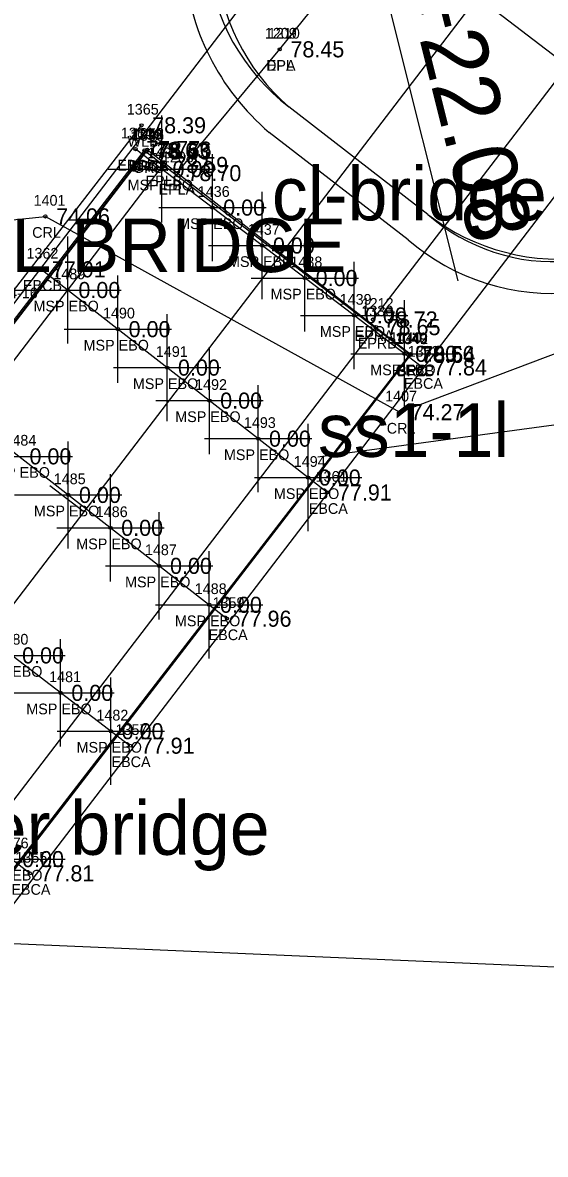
# Model space of a CAD drawing. Extents: x 2500794 to 2511032, y 910653 to 917533.
# Drawn here: x 2506099.6 to 2506148.4, y 913842.2 to 913947.8 of the extents above; entities that cross this region are included whole.
import ezdxf

# ---------------------------------------------------------------- set-up
doc = ezdxf.new("R2010")
doc.units = 0
for name, color, linetype in [('Default', 7, 'Continuous'), ('RD_EX_BldgApp', 7, 'Continuous'), ('RD_EX_Bridge', 7, 'Continuous'), ('RD_EX_Bridge_txCode', 7, 'Continuous'), ('RD_EX_Driveway_txCode', 7, 'Continuous'), ('RD_EX_GuardRail', 7, 'Continuous'), ('RD_EX_GuardRail_txCode', 7, 'Continuous'), ('RD_EX_H2O', 7, 'Continuous'), ('RD_EX_H2O_txCode', 7, 'Continuous'), ('RD_EX_Misc', 7, 'Continuous'), ('RD_EX_Misc_txCode', 7, 'Continuous'), ('RD_EX_Road', 7, 'Continuous'), ('RD_EX_Road_txCode', 7, 'Continuous'), ('RD_EX_TX_Bridge_ELEV', 7, 'Continuous'), ('RD_EX_TX_Driveway_ELEV', 7, 'Continuous'), ('RD_EX_TX_GuardRail_ELEV', 7, 'Continuous'), ('RD_EX_TX_H2O_ELEV', 7, 'Continuous'), ('RD_EX_TX_Misc_ELEV', 7, 'Continuous'), ('RD_EX_TX_Road_ELEV', 7, 'Continuous'), ('RD_EX_TX_UT_ELEV', 7, 'Continuous'), ('RD_EX_UT_txCode', 7, 'Continuous'), ('RD_HC_Cl', 7, 'Continuous'), ('RD_HC_Data', 7, 'Continuous'), ('RD_HC_Data_Tic', 7, 'Continuous'), ('RD_PD_Bridge', 7, 'Continuous'), ('RD_PD_CstnLmt', 7, 'Continuous'), ('RD_PD_Signals', 7, 'Continuous'), ('RD_SMD_Locator', 7, 'Continuous'), ('RD_XS_NPDES', 7, 'Continuous')]:
    doc.layers.add(name, color=color, linetype=linetype)

# ---------------------------------------------------------------- blocks, each defined once
blk = doc.blocks.new('POINT_DISPLAY')
at = {"layer": 'Default'}
blk.add_line((0, 0), (0, 0), dxfattribs=at)
blk = doc.blocks.new('Non-Wetland Waters (Tributaries)')
at = {"layer": 'Default'}
blk.add_lwpolyline([(636556.303, 232132.46), (636575.915, 232135.121), (636589.015, 232131.251), (636595.56, 232130.161)], dxfattribs=at)

msp = doc.modelspace()

# ---------------------------------------------------------------- linework, layer by layer
at = {"layer": 'RD_EX_BldgApp'}
msp.add_line((2506016.51, 913816.53), (2506110.72, 913938.26), dxfattribs=at)
at = {"layer": 'RD_EX_Bridge'}
for p, q in [((2506136.91, 913915.67), (2506110.17, 913936.04)), ((2506128.04, 913904), (2506101.37, 913924.82)), ((2506118.69, 913892.22), (2506092.16, 913912.92)), ((2506109.65, 913880.37), (2506082.8, 913900.86)), ((2506100.31, 913868.46), (2506073.74, 913889.05))]:
    msp.add_line(p, q, dxfattribs=at)
for points in [[(2506044.21, 913797.79), (2506019.43, 913816.8), (2506111, 913935.92), (2506135.82, 913916.84), (2506044.21, 913797.79)], [(2506111.24, 913935.99), (2506135.76, 913916.92), (2506044.08, 913798.01), (2506019.65, 913816.86), (2506111.24, 913935.99)]]:
    msp.add_lwpolyline(points, dxfattribs=at)
at = {"layer": 'RD_EX_GuardRail'}
for p, q in [((2506019.73, 913816.87), (2506111.18, 913935.82)), ((2506044.2, 913797.96), (2506135.82, 913916.84))]:
    msp.add_line(p, q, dxfattribs=at)
at = {"layer": 'RD_EX_H2O_txCode'}
msp.add_lwpolyline([(2505808.2, 913925.07), (2505825.64, 913915.36), (2505914.54, 913915.98), (2505996.26, 913926.38), (2506005.4, 913936.74), (2506012.64, 913937.08), (2506022.61, 913935.73), (2506047.54, 913912.75), (2506069, 913926.42), (2506101.76, 913929.76), (2506134.82, 913911.49), (2506168.31, 913924.14), (2506205.52, 913926.29), (2506300.04, 913899.96), (2506387.24, 913834.45), (2506403.62, 913708.7), (2506351.33, 913635.45), (2506287.73, 913577.34)], dxfattribs=at)
at = {"layer": 'RD_EX_Misc'}
for p, q in [((2506112.62, 913929.18), (2506112.62, 913939.18)), ((2506117.34, 913925.58), (2506117.34, 913935.58)), ((2506107.62, 913934.18), (2506117.62, 913934.18)), ((2506121.98, 913922.04), (2506121.98, 913932.04)), ((2506112.34, 913930.58), (2506122.34, 913930.58)), ((2506125.96, 913919.01), (2506125.96, 913929.01)), ((2506103.84, 913917.89), (2506103.84, 913927.89)), ((2506116.98, 913927.04), (2506126.98, 913927.04)), ((2506130.55, 913915.52), (2506130.55, 913925.52)), ((2506108.52, 913914.24), (2506108.52, 913924.24)), ((2506120.96, 913924.01), (2506130.96, 913924.01)), ((2506098.84, 913922.89), (2506108.84, 913922.89)), ((2506135.24, 913911.94), (2506135.24, 913921.94)), ((2506113.12, 913910.65), (2506113.12, 913920.65)), ((2506125.55, 913920.52), (2506135.55, 913920.52)), ((2506103.52, 913919.24), (2506113.52, 913919.24)), ((2506117.06, 913907.57), (2506117.06, 913917.57)), ((2506130.24, 913916.94), (2506140.24, 913916.94)), ((2506108.12, 913915.65), (2506118.12, 913915.65)), ((2506121.61, 913904.02), (2506121.61, 913914.02)), ((2506112.06, 913912.57), (2506122.06, 913912.57)), ((2506126.26, 913900.39), (2506126.26, 913910.39)), ((2506103.89, 913898.77), (2506103.89, 913908.77)), ((2506116.61, 913909.02), (2506126.61, 913909.02)), ((2506094.28, 913907.37), (2506104.28, 913907.37)), ((2506107.83, 913895.7), (2506107.83, 913905.7)), ((2506121.26, 913905.39), (2506131.26, 913905.39)), ((2506098.89, 913903.77), (2506108.89, 913903.77)), ((2506112.38, 913892.15), (2506112.38, 913902.15)), ((2506102.83, 913900.7), (2506112.83, 913900.7)), ((2506117.04, 913888.52), (2506117.04, 913898.52)), ((2506107.38, 913897.15), (2506117.38, 913897.15)), ((2506112.04, 913893.52), (2506122.04, 913893.52)), ((2506103.18, 913880.3), (2506103.18, 913890.3)), ((2506093.59, 913888.8), (2506103.59, 913888.8)), ((2506107.87, 913876.72), (2506107.87, 913886.72)), ((2506098.18, 913885.3), (2506108.18, 913885.3)), ((2506102.87, 913881.72), (2506112.87, 913881.72)), ((2506093.59, 913869.79), (2506103.59, 913869.79))]:
    msp.add_line(p, q, dxfattribs=at)
at = {"layer": 'RD_EX_Road'}
for points in [[(2506114.01, 913933.8), (2506123.61, 913945.35), (2506183.7, 914019.9), (2506246.75, 914102.24), (2506309.52, 914184.62), (2506366.78, 914260.38), (2506431.55, 914345.25), (2506455.95, 914376.74), (2506469.75, 914395.23), (2506492.7, 914425.08), (2506555.84, 914508.26), (2506617.75, 914589.02), (2506679.77, 914670.81), (2506740.35, 914750.22)], [(2506132.31, 913920.14), (2506200.99, 914009.83), (2506228.78, 914046.14), (2506238.19, 914058.36), (2506261.83, 914089.97), (2506324.5, 914172.22), (2506382.84, 914247.97), (2506424.88, 914303.73), (2506446.4, 914331.89), (2506508.34, 914413.09), (2506571.21, 914495.53), (2506633.01, 914576.81), (2506694.83, 914657.95), (2506756.78, 914739.18)], [(2506022.41, 913814.76), (2506062.45, 913868.71), (2506112.78, 913934.56)], [(2506041.83, 913800.29), (2506083.18, 913854.87), (2506132.58, 913919.43)]]:
    msp.add_lwpolyline(points, dxfattribs=at)
at = {"layer": 'RD_HC_Cl'}
for p, q in [((2505807.57, 913512.69), (2506748.89, 914743.92)), ((2505870.76, 913871.61), (2506259.06, 913855.07))]:
    msp.add_line(p, q, dxfattribs=at)
at = {"layer": 'RD_HC_Data'}
msp.add_line((2506112.07, 914036.23), (2506140.23, 913923.75), dxfattribs=at)
at = {"layer": 'RD_HC_Data_Tic'}
msp.add_line((2506105.36, 913902.19), (2506102.18, 913904.62), dxfattribs=at)
at = {"layer": 'RD_PD_Bridge'}
for p, q in [((2506007.09, 913801.65), (2506128.56, 913960.53)), ((2506155.57, 913939.88), (2506128.56, 913960.53)), ((2506034.1, 913781), (2506155.57, 913939.88))]:
    msp.add_line(p, q, dxfattribs=at)
at = {"layer": 'RD_PD_CstnLmt'}
msp.add_line((2506137.42, 913929.95), (2506124.47, 913939.97), dxfattribs=at)
for centre, radius, start, end in [((2506137.24, 913954.83), 19.59, 137.0924, 229.3275), ((2506149.09, 913943.18), 17.64, 228.5809, 321.497)]:
    msp.add_arc(centre, radius, start, end, dxfattribs=at)
at = {"layer": 'RD_PD_Signals'}
msp.add_line((2506137.42, 913929.95), (2506124.47, 913939.97), dxfattribs=at)
for centre, start, end in [((2506136.71, 913955.79), 140.0354, 232.2705), ((2506149.66, 913945.77), 232.2705, 325.1865)]:
    msp.add_arc(centre, 20, start, end, dxfattribs=at)
at = {"layer": 'RD_SMD_Locator'}
for centre in [(2506123.61, 913945.35), (2506123.61, 913945.35), (2506110.72, 913938.26), (2506110.17, 913936.04), (2506111, 913935.92), (2506111.18, 913935.82), (2506111.24, 913935.99), (2506111.24, 913935.99), (2506112.78, 913934.56), (2506112.62, 913934.18), (2506114.01, 913933.8), (2506117.34, 913930.58), (2506101.76, 913929.76), (2506121.98, 913927.04), (2506101.37, 913924.82), (2506125.96, 913924.01), (2506103.84, 913922.89), (2506130.55, 913920.52), (2506132.31, 913920.14), (2506108.52, 913919.24), (2506132.58, 913919.43), (2506135.24, 913916.94), (2506135.76, 913916.92), (2506135.82, 913916.84), (2506135.82, 913916.84), (2506113.12, 913915.65), (2506136.91, 913915.67), (2506117.06, 913912.57), (2506134.82, 913911.49), (2506121.61, 913909.02), (2506126.26, 913905.39), (2506103.89, 913903.77), (2506128.04, 913904), (2506107.83, 913900.7), (2506112.38, 913897.15), (2506117.04, 913893.52), (2506118.69, 913892.22), (2506103.18, 913885.3), (2506107.87, 913881.72), (2506109.65, 913880.37), (2506100.31, 913868.46)]:
    msp.add_circle(centre, 0.15, dxfattribs=at)
at = {"layer": 'RD_XS_NPDES'}
msp.add_line((2506135.58, 913927.58), (2506122.64, 913937.6), dxfattribs=at)
for centre, radius, start, end in [((2506137.26, 913954.83), 22.6, 137.4459, 229.681), ((2506149.08, 913943.2), 20.64, 229.1605, 322.0766)]:
    msp.add_arc(centre, radius, start, end, dxfattribs=at)

# ---------------------------------------------------------------- block references
at = {"layer": 'Default', "xscale": 3.937007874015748, "yscale": 3.937007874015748}
for name, p in [('Non-Wetland Waters (Tributaries)', (0, 0)), ('POINT_DISPLAY', (2506122.88, 913929.39)), ('POINT_DISPLAY', (2506122.88, 913929.39)), ('POINT_DISPLAY', (2506127.18, 913907.32)), ('POINT_DISPLAY', (2506127.18, 913907.32))]:
    msp.add_blockref(name, p, dxfattribs=at)
at = {"layer": 'RD_EX_H2O', "xscale": 3.937007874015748, "yscale": 3.937007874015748}
msp.add_blockref('Non-Wetland Waters (Tributaries)', (0, 0), dxfattribs=at)

# ---------------------------------------------------------------- texts
at = {"layer": 'Default'}
for s, p in [('cl-bridge 1', (2506122.88, 913929.39)), ('cl-bridge 1', (2506122.88, 913929.39)), ('S2-9L BRIDGE', (2506084.48, 913924.56)), ('S2-9L BRIDGE', (2506084.48, 913924.56)), ('ss1-1l', (2506127.18, 913907.32)), ('ss1-1l', (2506127.18, 913907.32)), ('cl/center bridge', (2506076.96, 913870.19)), ('cl/center bridge', (2506076.96, 913870.19))]:
    msp.add_text(s, height=5, dxfattribs=at).set_placement(p)
at = {"layer": 'RD_EX_Bridge_txCode'}
for s, p in [('1364', (2506108.8, 913937.04)), ('1339', (2506109.66, 913936.92)), ('1048', (2506109.85, 913936.99)), ('1052', (2506109.85, 913936.99)), ('EBCB', (2506108.47, 913934.04)), ('BRCA', (2506109.5, 913933.99)), ('BRCB', (2506109.52, 913933.99)), ('BRC', (2506109.75, 913933.92)), ('1362', (2506100, 913925.82)), ('EBCB', (2506099.67, 913922.82)), ('1049', (2506134.38, 913917.92)), ('1340', (2506134.43, 913917.84)), ('1363', (2506135.54, 913916.67)), ('BRC', (2506134.51, 913914.92)), ('BRC', (2506134.56, 913914.84)), ('EBCA', (2506135.19, 913913.67)), ('1361', (2506126.95, 913905)), ('EBCA', (2506126.32, 913902)), ('1359', (2506117.35, 913893.22)), ('EBCA', (2506116.98, 913890.22)), ('1357', (2506108.3, 913881.37)), ('EBCA', (2506107.93, 913878.37)), ('1355', (2506098.96, 913869.46)), ('EBCA', (2506098.59, 913866.46))]:
    msp.add_text(s, height=1, dxfattribs=at).set_placement(p)
at = {"layer": 'RD_EX_Driveway_txCode'}
for s, p in [('1210', (2506122.51, 913946.35)), ('DPA', (2506122.34, 913943.35))]:
    msp.add_text(s, height=1, dxfattribs=at).set_placement(p)
at = {"layer": 'RD_EX_GuardRail_txCode'}
for s, p in [('1338', (2506109.83, 913936.82)), ('GRB', (2506109.92, 913933.82)), ('1342', (2506134.47, 913917.84)), ('GR1B', (2506134.4, 913914.84))]:
    msp.add_text(s, height=1, dxfattribs=at).set_placement(p)
at = {"layer": 'RD_EX_H2O_txCode'}
for s, p in [('1401', (2506100.66, 913930.76)), ('CRL', (2506100.53, 913927.76)), ('odw  12-14-16', (2506092.5, 913922.12)), ('1407', (2506133.44, 913912.49)), ('CRL', (2506133.59, 913909.49))]:
    msp.add_text(s, height=1, dxfattribs=at).set_placement(p)
at = {"layer": 'RD_EX_Misc_txCode'}
for s, p in [('1435', (2506111.28, 913935.18)), ('MSP EBO', (2506109.43, 913932.18)), ('1436', (2506115.97, 913931.58)), ('MSP EBO', (2506114.14, 913928.58)), ('1437', (2506120.64, 913928.04)), ('MSP EBO', (2506118.79, 913925.04)), ('1438', (2506124.61, 913925.01)), ('1489', (2506102.5, 913923.89)), ('MSP EBO', (2506122.76, 913922.01)), ('MSP EBO', (2506100.65, 913920.89)), ('1439', (2506129.2, 913921.52)), ('1490', (2506107.13, 913920.24)), ('MSP EBO', (2506127.35, 913918.52)), ('1440', (2506133.86, 913917.94)), ('MSP EBO', (2506105.32, 913917.24)), ('1491', (2506112.06, 913916.65)), ('MSP EBO', (2506132.05, 913914.94)), ('MSP EBO', (2506109.92, 913913.65)), ('1492', (2506115.72, 913913.57)), ('MSP EBO', (2506113.87, 913910.57)), ('1493', (2506120.27, 913910.02)), ('1484', (2506097.94, 913908.37)), ('MSP EBO', (2506118.41, 913907.02)), ('1494', (2506124.92, 913906.39)), ('MSP EBO', (2506096.09, 913905.37)), ('1485', (2506102.54, 913904.77)), ('MSP EBO', (2506123.07, 913903.39)), ('MSP EBO', (2506100.69, 913901.77)), ('1486', (2506106.46, 913901.7)), ('MSP EBO', (2506104.64, 913898.7)), ('1487', (2506111.04, 913898.15)), ('MSP EBO', (2506109.19, 913895.15)), ('1488', (2506115.69, 913894.52)), ('MSP EBO', (2506113.84, 913891.52)), ('1480', (2506097.2, 913889.8)), ('MSP EBO', (2506095.39, 913886.8)), ('1481', (2506102.11, 913886.3)), ('MSP EBO', (2506099.98, 913883.3)), ('1482', (2506106.52, 913882.72)), ('MSP EBO', (2506104.67, 913879.72)), ('1476', (2506097.22, 913870.79)), ('MSP EBO', (2506095.4, 913867.79))]:
    msp.add_text(s, height=1, dxfattribs=at).set_placement(p)
at = {"layer": 'RD_EX_Road_txCode'}
for s, p in [('1209', (2506122.22, 913946.35)), ('EPL', (2506122.4, 913943.35)), ('1337', (2506111.44, 913935.56)), ('1208', (2506112.62, 913934.8)), ('EPLB', (2506111.1, 913932.56)), ('EPLA', (2506112.31, 913931.8)), ('1212', (2506131.25, 913921.14)), ('1336', (2506131.21, 913920.43)), ('EPRA', (2506130.59, 913918.14)), ('EPRB', (2506130.88, 913917.43))]:
    msp.add_text(s, height=1, dxfattribs=at).set_placement(p)
at = {"layer": 'RD_EX_TX_Bridge_ELEV'}
for s, p in [('77.77', (2506111.17, 913935.29)), ('78.63', (2506112, 913935.17)), ('78.56', (2506112.24, 913935.24)), ('78.56', (2506112.24, 913935.24)), ('77.91', (2506102.37, 913924.07)), ('78.56', (2506136.76, 913916.17)), ('78.64', (2506136.82, 913916.09)), ('77.84', (2506137.91, 913914.92)), ('77.91', (2506129.04, 913903.25)), ('77.96', (2506119.69, 913891.47)), ('77.91', (2506110.65, 913879.62)), ('77.81', (2506101.31, 913867.71))]:
    msp.add_text(s, height=1.5, dxfattribs=at).set_placement(p)
at = {"layer": 'RD_EX_TX_Driveway_ELEV'}
msp.add_text('78.45', height=1.5, dxfattribs=at).set_placement((2506124.61, 913944.6))
at = {"layer": 'RD_EX_TX_GuardRail_ELEV'}
for s, p in [('78.63', (2506112.18, 913935.07)), ('78.64', (2506136.82, 913916.09))]:
    msp.add_text(s, height=1.5, dxfattribs=at).set_placement(p)
at = {"layer": 'RD_EX_TX_H2O_ELEV'}
for s, p in [('74.06', (2506102.76, 913929.01)), ('74.27', (2506135.82, 913910.74))]:
    msp.add_text(s, height=1.5, dxfattribs=at).set_placement(p)
at = {"layer": 'RD_EX_TX_Misc_ELEV'}
for p in [(2506113.62, 913933.43), (2506118.34, 913929.83), (2506122.98, 913926.29), (2506126.96, 913923.26), (2506104.84, 913922.14), (2506131.55, 913919.77), (2506109.52, 913918.49), (2506136.24, 913916.19), (2506114.12, 913914.9), (2506118.06, 913911.82), (2506122.61, 913908.27), (2506100.28, 913906.62), (2506127.26, 913904.64), (2506104.89, 913903.02), (2506108.83, 913899.95), (2506113.38, 913896.4), (2506118.04, 913892.77), (2506099.59, 913888.05), (2506104.18, 913884.55), (2506108.87, 913880.97), (2506099.59, 913869.04)]:
    msp.add_text('0.00', height=1.5, dxfattribs=at).set_placement(p)
at = {"layer": 'RD_EX_TX_Road_ELEV'}
for s, p in [('78.45', (2506124.61, 913944.6)), ('78.59', (2506113.78, 913933.81)), ('78.70', (2506115.01, 913933.05)), ('78.72', (2506133.31, 913919.39)), ('78.65', (2506133.58, 913918.68))]:
    msp.add_text(s, height=1.5, dxfattribs=at).set_placement(p)
at = {"layer": 'RD_EX_TX_UT_ELEV'}
msp.add_text('78.39', height=1.5, dxfattribs=at).set_placement((2506111.72, 913937.51))
at = {"layer": 'RD_EX_UT_txCode'}
for s, p in [('1365', (2506109.35, 913939.26)), ('WLB', (2506109.42, 913936.26))]:
    msp.add_text(s, height=1, dxfattribs=at).set_placement(p)
at = {"layer": 'RD_HC_Data'}
msp.add_text('PI =11+22.08', height=6, rotation=284.0539, dxfattribs=at).set_placement((2506129.79, 913973.66))

doc.saveas('drawing.dxf')
